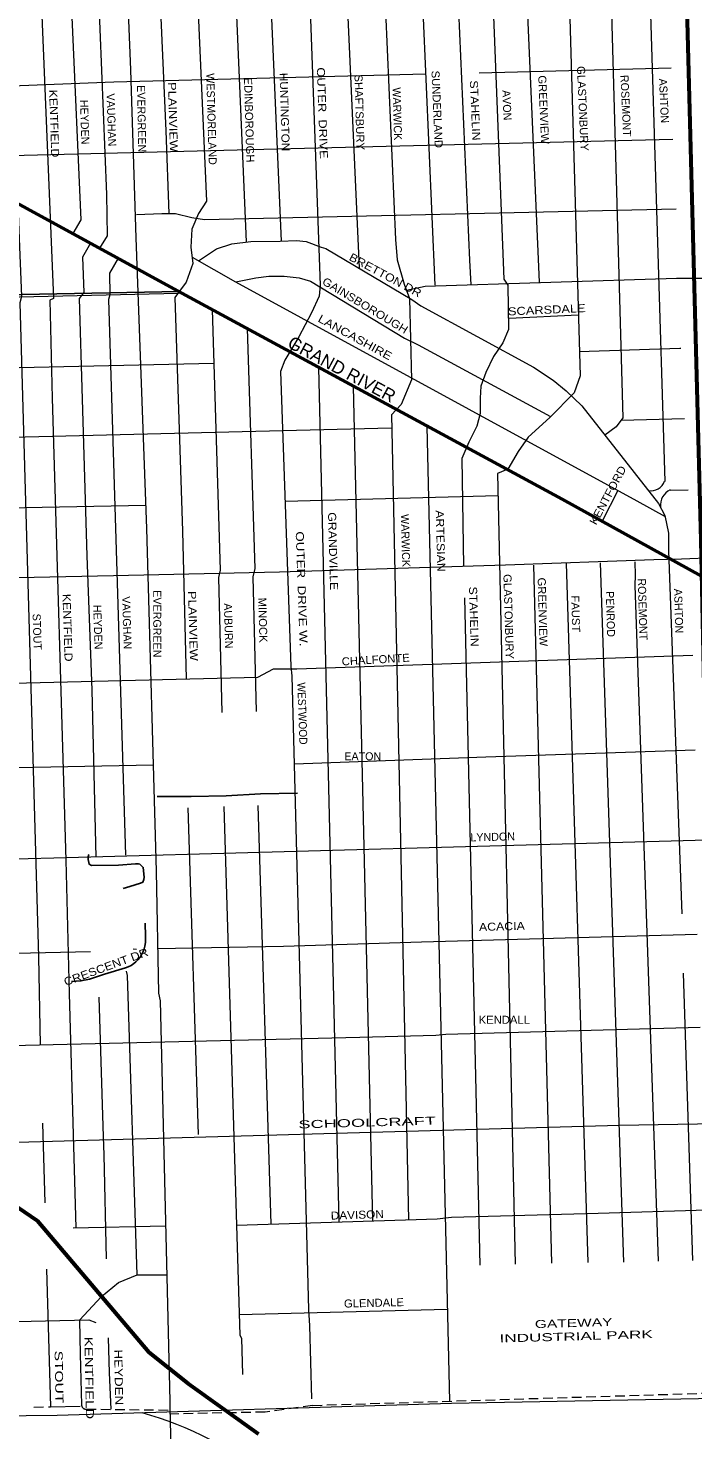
# Model space of a CAD drawing. Extents: x 34705 to 138605, y 34275 to 143551.
# Drawn here: x 47356 to 53584, y 117233 to 130370 of the extents above; entities that cross this region are included whole.
import ezdxf
from ezdxf.enums import TextEntityAlignment as Align

# ---------------------------------------------------------------- set-up
doc = ezdxf.new("R2010")
doc.units = 0
doc.header["$LTSCALE"] = 30
doc.linetypes.add('MEDIUM_DASHED', pattern=[4.5, 3, -1.5])
for name, color, linetype, lineweight in [('1', 7, 'Continuous', 13), ('11', 7, 'Continuous', 13), ('50', 7, 'Continuous', 13), ('51', 7, 'Continuous', 35)]:
    doc.layers.add(name, color=color, linetype=linetype, lineweight=lineweight)

msp = doc.modelspace()

# ---------------------------------------------------------------- linework, layer by layer
at = {"layer": '1'}
for p, q in [((49304.96, 130558.77), (49398.21, 128367.84)), ((51580.15, 129951.72), (53380.26, 129996.04)), ((49690.15, 129237.44), (53395.5, 129328)), ((46965.59, 129170.84), (49690.15, 129237.44)), ((51862.66, 127650.97), (52509.93, 127683.62)), ((50077.4, 127188.53), (50267.04, 119181.8)), ((50401.89, 127011.78), (50583, 119191.55)), ((52912.65, 126696.93), (53505.01, 126712.35)), ((51090.94, 126636.46), (51303.21, 117503.32)), ((49762.77, 125936.65), (51758.31, 125988.55)), ((52881.43, 126035.06), (52734.59, 125747.68)), ((53370.11, 126040.95), (53538.2, 126041.75)), ((52091.27, 125336.15), (52257.78, 118796.38)), ((52396.53, 125354.65), (52600.04, 118801.01)), ((52715.67, 125359.28), (52933.05, 118805.64)), ((51443.75, 125030.79), (51587.13, 118777.88)), ((48851.37, 123061.39), (48948.86, 120000.3)), ((49509.03, 123084.07), (49629.71, 119162.13)), ((53492.69, 121513.38), (53580.57, 118819.52)), ((47490.8, 120108.42), (47511.94, 119361.32)), ((47778.92, 119126.79), (48643.91, 119146.42)), ((47529.54, 118739.38), (47566.04, 117449.74)), ((47836.51, 118262.23), (48044.01, 118484.56)), ((48661.33, 118295.02), (48663.92, 118295.08)), ((49334.27, 118315.58), (51283.2, 118364.43)), ((47566.84, 117449.76), (47844.57, 117454.6))]:
    msp.add_line(p, q, dxfattribs=at)
at = {"layer": '1', "linetype": 'MEDIUM_DASHED'}
for p, q in [((48341.64, 121740.59), (48372.62, 121739.98)), ((50021.11, 117463.52), (53735.07, 117578.79)), ((47410.79, 117447.04), (47566.04, 117449.75)), ((47902.25, 117428.81), (48685.37, 117419.43))]:
    msp.add_line(p, q, dxfattribs=at)
at = {"layer": '1'}
for points in [[(47981.66, 141004.05), (48033.09, 139024.1), (48053.24, 138456.35), (48093.94, 137313.03), (48126.32, 135471.37), (48232.15, 132077.43), (48314.67, 129978.44), (48365.06, 128404.34), (48465.85, 125680.25), (48556.56, 122467.79), (48576.72, 121326.61), (48594.36, 121253.51), (48682.55, 117502.92), (48684.81, 117442.73), (48828.7, 111512.8), (48828.7, 111406.94), (48844.83, 109618.16), (48844.83, 109449.36), (48894.21, 107747.71), (49053.86, 101630.72)], [(51025.33, 141090.87), (51046.5, 140457.26), (50973.36, 140455.6), (51010.61, 138518.99), (51040.79, 138519.68), (51096.86, 136138.2), (51101.49, 135933.48), (51166.24, 135845.57), (51226.37, 133420.05), (51235.62, 133336.77), (51244.87, 133295.13), (51263.37, 133221.11), (51314.25, 130944.79), (51346.62, 130863.83), (51379, 130748.16), (51490, 128194.25), (51502.9, 127965.17)], [(50249.89, 135848.29), (50319.84, 133240.76), (50338.34, 133180.62), (50393.84, 130623.24), (50347.59, 130539.96), (50456.7, 128119.39)], [(50573.64, 135857.98), (50643.6, 133250.02), (50657.47, 133208.38), (50722.23, 130646.38), (50703.73, 130526.08), (50796.23, 128387.42), (50814.73, 128197.73), (50879.48, 127971.02), (50930.36, 127836.85), (50948.86, 127073.45), (50851.73, 126842.12), (50759.23, 126744.96), (50920.25, 119201.95)], [(50874.64, 135866.99), (50944.23, 133393.44), (50962.73, 133277.78), (50976.61, 133199.12), (51027.49, 130873.08), (51055.24, 130757.42), (51055.24, 130535.34), (51166.24, 127961.77)], [(52076.71, 135899.81), (52123.65, 133758.95), (52193.02, 130870.77), (52169.9, 130799.06), (52077.4, 130789.8), (52021.89, 130780.55), (52142.15, 127989.53)], [(47308.76, 135760.25), (47350.4, 134258.27), (47382.45, 133279.02), (47419.09, 132217.31), (47462.6, 131018.74), (47595.41, 127835.9), (47561.07, 127818.72), (47581.67, 126900.18), (47709.91, 122571.45), (47741.39, 121322.48), (47780.32, 119892.55), (47802.67, 119126.89)], [(47601.7, 135769.02), (47610.36, 135470.69), (47650.37, 134155.19), (47677.85, 133301.93), (47748.84, 131000.41), (47764.87, 130472.42), (47849.59, 128573.49), (47775.79, 128444.97)], [(47852.57, 135776.53), (47870.93, 135457.68), (47906.84, 134178.1), (47936.61, 133279.02), (47973.25, 132219.6), (48012.18, 130750.73), (48090.03, 128810.56), (48096.9, 128422.3), (48026.31, 128308.23)], [(47021.15, 134479.41), (47155.75, 130537.71), (47192.39, 130418.59), (47293.15, 127855.37), (47279.41, 127795.82), (47452.87, 121666.08), (47468.78, 120842.41)], [(49945.58, 134492.76), (50040.7, 130850.55), (50005.42, 130782.5), (49997.86, 130540.52), (50093.61, 127959.47), (50083.53, 127858.64), (50010.46, 127699.85), (49892.03, 127475.52), (49761.01, 127256.23), (49720.69, 127152.26), (49816.44, 124386.57), (49826.52, 124298.35), (49982.74, 118358.02), (49992.82, 118211.82), (50011.81, 117525.07)], [(48490.61, 133169.11), (48521.92, 132064.83), (48566.64, 130621.18), (48599.4, 130464.91), (48647.27, 129406.27), (48674.42, 128632.53)], [(49655.33, 133193.56), (49718.17, 130911.05), (49640.06, 130790.06), (49627.46, 130679.15), (49727.69, 128374.34)], [(51601, 131284.86), (51605.63, 130956.36), (51633.38, 130877.71), (51679.63, 130831.44), (51707.38, 130720.4), (51813.76, 128017.29), (51850.76, 127961.77), (51855.39, 127545.37), (51804.51, 127420.45), (51716.63, 127290.9), (51642.63, 127142.85), (51596.38, 127013.3), (51591.75, 126902.26), (51591.75, 126758.84), (51559.38, 126638.54), (51485.38, 126490.49), (51420.62, 126337.81), (51434.26, 125327.84)], [(52553.79, 131261.72), (52553.79, 131021.14), (52526.04, 130956.36), (52489.03, 130896.22), (52456.66, 130812.94), (52456.66, 130664.88), (52433.53, 130609.36), (52428.91, 130567.72), (52526.04, 127110.46), (52470.53, 126953.16), (52243.9, 126721.82), (52040.39, 126536.76), (51947.89, 126402.59), (51850.76, 126236.03), (51753.63, 126196.7), (51920.14, 118787.13)], [(52882.17, 131270.98), (52891.42, 130998), (52859.05, 130910.1), (52812.79, 130845.32), (52928.42, 126717.2), (52863.67, 126633.92), (52759.2, 126555.53)], [(53192.06, 131284.86), (53201.31, 130896.22), (53192.06, 130849.95), (53178.18, 130808.31), (53320.03, 126122.33)], [(48948.84, 130538.06), (48949.65, 130511.53), (49027.76, 128748.4), (48952.16, 128632.46), (48889.17, 128486.27), (48881.61, 128317.39), (48899.25, 128163.63), (48836.26, 127989.71), (48783.34, 127916.62), (48730.43, 127843.52), (48803.5, 125655.04), (48835.71, 124271.35)], [(46047.64, 129793.56), (46960.31, 129819.95), (48157.87, 129867.44), (51080.94, 129939.42)], [(48371.53, 128622), (48608.93, 128632.55), (48735.55, 128632.55), (48888.54, 128595.61), (49009.88, 128574.5), (53425.77, 128674.66)], [(50901.75, 127912.29), (51076.59, 127951.78), (53429.51, 128025.66), (53735.5, 128025.66), (58802.7, 128162.87), (59905.3, 128215.65), (61846.72, 128284.25), (63556.01, 128358.13), (63587.66, 128358.13), (64447.59, 128389.8), (65614.81, 128410.91), (67682.84, 128463.68), (68864.58, 128479.51), (72639.26, 128541.52), (73551.93, 128552.07), (74601.78, 128562.63), (77161.76, 128625.95), (79066.25, 128678.73), (79790.99, 128701.73)], [(47939.8, 128355.45), (47865.62, 128221.87), (47879.36, 127892.02), (47835.85, 127834.76), (47863.33, 126891.01), (47906.84, 125424.43), (47953.33, 124166.79), (47991.26, 122600.09)], [(48951.23, 128189.26), (49120.67, 128300.08), (49263.11, 128347.58), (49442.48, 128368.69), (49716.81, 128373.97), (49869.8, 128379.24), (49959.49, 128368.69), (50101.93, 128315.92), (50144.13, 128305.36), (50951.3, 127825.13), (51035.71, 127767.08), (52090.83, 127191.85), (52275.48, 127070.47), (52396.81, 126970.2), (52543.21, 126830.36), (53261.72, 125916.12)], [(48892.49, 128222.59), (49300.04, 127991.37), (49912.01, 127658.9), (53057.74, 125938.65), (53323.67, 125792.57)], [(48200.28, 128213.28), (48118.13, 128072.89), (48123.17, 127868.73), (48110.57, 127825.88), (48269.31, 122620.29)], [(49301.46, 127990.6), (49489.96, 128028.31), (49611.3, 128044.14), (49753.74, 128044.14), (49896.18, 128028.31), (50001.69, 127996.64), (50882.72, 127463.63), (51009.33, 127400.31), (52250.44, 126728.5)], [(41439.59, 127717.9), (41636.79, 127718.72), (41865.41, 127714.3), (42250.53, 127714.3), (43127.6, 127724.86), (43217.28, 127756.52), (48761.16, 127885.97)], [(49080.47, 127731.54), (49156.26, 125291.45), (49138.63, 125220.88), (49171.38, 123954.93)], [(49407.75, 127553.27), (49478.79, 125304.06), (49461.15, 125228.44), (49491.39, 123965.01)], [(52519.62, 127338.98), (53461.16, 127371.28), (53471.43, 127371.51)], [(39016.09, 127054.55), (40477.93, 127075.75), (40562.34, 127081.02), (42883.6, 127086.3), (44889.65, 127144.35), (45000.43, 127144.35), (46145.24, 127165.46), (49096.07, 127229.34)], [(39035.59, 126401.44), (40724.71, 126427.53), (41115.04, 126427.53), (41916.92, 126427.53), (42580.01, 126431.39), (43166, 126439.1), (44149.07, 126462.24), (50761.79, 126624.85)], [(39073.76, 125736.85), (40516.53, 125764.23), (40612.91, 125764.23), (40829.76, 125768.08), (41180.58, 125764.23), (41862.94, 125764.23), (42583.86, 125764.23), (43285.51, 125779.65), (44496.99, 125814.36), (45807.75, 125852.92), (46189.42, 125856.78), (48457.74, 125899.57)], [(53261.71, 125916.12), (53321.56, 125803.44), (53353.94, 125636.88), (53353.94, 125470.32), (53478.82, 122068.58)], [(39941.51, 125093.75), (40528.09, 125108.63), (40663.03, 125097.06), (40744.94, 125108.63), (41581.52, 125112.49), (42287.01, 125112.49), (43300.93, 125116.35), (44878.65, 125170.34), (48156.52, 125239.75), (49710.15, 125274.46), (51827.61, 125340.02), (53217.9, 125389.91), (53477.78, 125395.11), (53786.04, 125409.43)], [(53039.43, 125368.53), (53044.05, 125243.61), (53039.43, 125146.45), (53256.81, 118814.89)], [(40914.75, 124129.1), (43212.26, 124136.81), (43354.9, 124132.95), (44281.1, 124159.95), (49507.13, 124287.78), (49653.37, 124366.55), (49872.73, 124366.55), (53583.68, 124493.23)], [(46916.68, 119921.92), (52891.98, 120088.09), (53990.71, 120107.37), (55409.41, 120130.51), (55891.31, 120149.79), (57164.48, 120188.36), (57866.12, 120199.93), (58563.91, 120223.06), (59011.11, 120234.63), (60333.44, 120284.77), (62664.85, 120381.18), (62942.42, 120535.44), (65811.63, 120620.28), (69640.78, 120751.4), (73304.16, 120847.81), (73350.43, 120847.81), (73385.12, 120959.64), (73489.21, 121113.9), (73728.23, 121252.73), (77495.7, 123154.91), (77576.66, 123220.47), (77676.9, 123382.44), (77895.97, 123692.55)], [(49852.8, 123476.41), (51645.45, 123541.96), (53604.5, 123605.39)], [(40933.12, 123337.57), (41905.35, 123337.57), (41978.6, 123333.72), (43223.82, 123341.43), (43362.61, 123337.57), (44543.25, 123376.14), (44998.16, 123391.56), (45869.44, 123418.56), (45965.82, 123414.7), (48528.39, 123465.41)], [(49189.02, 123073.99), (49340.21, 118121.08), (49355.33, 118093.36), (49363.22, 117751.65)], [(41099.62, 122454.45), (41458.15, 122462.16), (41766.57, 122469.88), (42005.59, 122473.73), (43281.65, 122493.01), (43412.73, 122485.3), (47717.02, 122597.14), (53834.22, 122766.82), (57551.33, 122855.98)], [(48569.31, 121745.04), (49749.94, 121768.07), (51041.43, 121806.63), (53623.93, 121880.52)], [(41430.27, 121772.11), (41639.34, 121602.18), (41701.03, 121575.18), (41824.39, 121571.33), (41959.32, 121582.9), (42028.72, 121590.61), (43250.81, 121617.6), (43408.87, 121613.75), (44011.24, 121629.17), (47939.67, 121717.87)], [(48274.35, 121533.3), (48284.43, 121492.97), (48375.94, 118687.65)], [(48284.31, 121493.44), (48284.43, 121492.97), (48375.94, 118687.65)], [(48020.24, 121288.1), (48059.69, 119980.74), (48064.27, 119811.23), (48088.34, 118835.59)], [(41106.93, 120675.49), (41284.67, 120679.54), (41450.44, 120683.39), (41674.04, 120687.25), (41781.99, 120691.1), (41959.32, 120714.24), (42051.85, 120718.1), (43281.65, 120741.24), (50463.84, 120914.78), (51177.05, 120934.06), (51269.57, 120941.77), (53653.08, 121008.37)], [(49308.73, 119152.22), (51188.61, 119210.23), (51323.54, 119225.66), (52696.95, 119264.22), (53718.57, 119295.08), (53733.85, 119295.33)], [(48044.01, 118484.56), (48203.94, 118615.99), (48376.45, 118687.67), (48654.04, 118687.68)], [(46026.05, 118221.66), (47924.77, 118264.2), (47989.98, 118241.07)], [(47836.51, 118262.23), (47844.87, 117942.07), (47857.16, 117469.03)], [(48106.54, 118097.8), (48114.65, 117769.13), (48129.68, 117427.52)]]:
    msp.add_lwpolyline(points, dxfattribs=at)
at = {"layer": '1', "lineweight": 53}
msp.add_lwpolyline([(35051.57, 135383.85), (35124.2, 135323.83), (40544.24, 132389.75), (44352.38, 130313.49), (48721.15, 127927.26), (52359.24, 125955.06), (53781.74, 125169.15), (55156.63, 124418.97), (56043.46, 123936.71), (56442.24, 123716.41), (57585, 123085.31), (70109.98, 116247.42), (80624.23, 110526.89), (82336.58, 109591.28)], dxfattribs=at)
at = {"layer": '1', "lineweight": 25}
for points in [[(37911.41, 127686.12), (38203.24, 127680.58), (38303.04, 127721.95), (38325.81, 127931.49), (38521.05, 128243.98), (39412.67, 127885.92), (39479.2, 127912.86), (39529.81, 127990.08), (39707.77, 127962.88), (39975.21, 127996.38), (40834.68, 127905.45), (41055.96, 127944.51), (41290.17, 127858.28), (41387.87, 127762.23), (48773.97, 127901.51)], [(48563.94, 123168.62), (48883.43, 123167.71), (49211.61, 123174.76), (49532.23, 123195), (49878.42, 123199.25)], [(47924.01, 122624.47), (47919.96, 122603.4), (47919.77, 122579.48), (47923.79, 122551.2), (47928.45, 122534.15), (47951.38, 122521.37), (48202.18, 122527.02)], [(48202.18, 122527.02), (48362.93, 122537.84), (48389.12, 122538.94), (48404.19, 122534.48), (48434.86, 122504.15), (48441.87, 122412.8), (48439.7, 122392.72), (48431.18, 122365.49), (48410.43, 122355.68), (48308.4, 122326.42), (48246.54, 122306.73)], [(48268.7, 121564.82), (48292.08, 121572.17), (48321.15, 121586.35), (48348.11, 121604.14), (48366.69, 121619.73), (48383.7, 121637.02), (48405.53, 121664.63), (48419.25, 121686.08), (48434.33, 121716.49), (48443.11, 121740.37), (48450.08, 121766.25), (48454.63, 121801.69), (48456.9, 121859.85), (48453.91, 121982.49)], [(47762.5, 121436.14), (47850.93, 121440.17), (47932.05, 121458.72), (48073.38, 121504.41), (48268.7, 121564.82)]]:
    msp.add_lwpolyline(points, dxfattribs=at)
at = {"layer": '1', "linetype": 'MEDIUM_DASHED'}
msp.add_lwpolyline([(50021.11, 117463.52), (49576.83, 117400.51), (48686.29, 117381.76)], dxfattribs=at)
at = {"layer": '1'}
for centre, radius, start, end in [((53190.67, 126172.47), 137.66, 260.60799, 338.69952), ((53437.08, 125899.04), 157.01, 115.05434, 186.39927)]:
    msp.add_arc(centre, radius, start, end, dxfattribs=at)
at = {"layer": '1', "linetype": 'MEDIUM_DASHED'}
msp.add_arc((47896.86, 117468.06), 39.62, 178.6386, 277.81809, dxfattribs=at)
at = {"layer": '50'}
msp.add_lwpolyline([(65035.62, 117740.68), (51320.84, 117480.65), (47627.27, 117368.44), (46180.25, 117354.42), (45362.54, 117350.68), (43373.91, 117338.95), (42070.05, 117290.03), (40546.95, 117248.5)], dxfattribs=at)
msp.add_arc((47551.28, 114253.58), 3258.47, 50.45194, 74.44351, dxfattribs=at)
at = {"layer": '51', "lineweight": 60}
for points in [[(53247.59, 141475.55), (53367.81, 136119.69), (53437.19, 134090.91), (53460.32, 134053.9), (53501.94, 131503.46), (53659.2, 125572.1), (53705.45, 123295.79), (53737.83, 121494.87), (53784.08, 121152.5), (53816.45, 120138.11), (53862.7, 118347.6), (53920.69, 117583.67), (53996.83, 116839.32), (53996.26, 116300.14), (54017.35, 115245.27), (54103.21, 113517.38), (54126.34, 110285.67), (54140.21, 108707.98), (54144.84, 108035.97), (54101.7, 107394.41), (54140.21, 105981.73), (54195.72, 103679.98), (54256.6, 101226.04)], [(37691, 119648.31), (39355.56, 119744.01), (39542.31, 119764.02), (39842.43, 119790.71), (42090.07, 119804.05), (42470.23, 119764.02), (43463.99, 119710.65), (46426.92, 119697.3), (46586.99, 119657.27), (46840.43, 119557.2), (47133.89, 119403.75), (47440.69, 119196.93), (48487.8, 117962.66), (48854.63, 117669.11), (49514.91, 117195.42)]]:
    msp.add_lwpolyline(points, dxfattribs=at)

# ---------------------------------------------------------------- texts
at = {"layer": '11'}
for s, height, rotation, p in [('WESTMORELAND', 75, 271.61, (49036.8, 129516.26)), ('EVERGREEN', 75, 271.007, (48382.11, 129520.14)), ('WARWICK', 75, 271.611, (50777.46, 129565.39)), ('ROSEMONT', 75, 272.539, (52917.45, 129639.61)), ('ASHTON', 75, 272.537, (53275.01, 129686.58)), ('HEYDEN', 75, 271.867, (47849.08, 129487.26)), ('VAUGHAN', 75, 271.867, (48099.34, 129508.17)), ('AVON', 75, 272.539, (51804.28, 129645.42)), ('GRAND RIVER', 120, 331.683, (50267.09, 127119.89)), ('WARWICK', 75, 271.579, (50854.24, 125566.56)), ('ROSEMONT', 75, 271.653, (53075.5, 124922.37)), ('EVERGREEN', 75, 270, (48528.58, 124786.66)), ('PENROD', 75, 271.656, (52774.07, 124877.21)), ('ASHTON', 75, 271.654, (53413.13, 124906.69)), ('HEYDEN', 75, 271.867, (47972.66, 124755.14)), ('VAUGHAN', 75, 271.867, (48244.49, 124796.11)), ('AUBURN', 75, 271.579, (49196.31, 124767.44)), ('STOUT', 75, 271.868, (47403.68, 124711.1)), ('LYNDON', 75, 1.58, (51709.02, 122753.25))]:
    msp.add_text(s, height=height, rotation=rotation, dxfattribs=at).set_placement(p, align=Align.CENTER)
for s, rotation, width, p in [('HUNTINGTON', 271.611, 1.1, (49722.38, 129581.81)), ('OUTER  DRIVE', 271.983, 1.2, (50075.5, 129572.65)), ('SHAFTSBURY', 271.609, 1.05, (50423.24, 129580.16)), ('SUNDERLAND', 272.538, 1.05, (51150.27, 129606.71)), ('GLASTONBURY', 272.539, 1.05, (52514.87, 129614.33)), ('PLAINVIEW', 271.611, 1.2, (48675.89, 129534.67)), ('EDINBOROUGH', 271.611, 1.05, (49389.93, 129507.44)), ('STAHELIN', 272.54, 1.15, (51506.3, 129596.11)), ('GREENVIEW', 272.537, 1.05, (52148.2, 129603.66)), ('KENTFIELD', 271.867, 1.15, (47563.5, 129474.42)), ('BRETTON DR', 331.684, 1.15, (50685.3, 128021.94)), ('GAINSBOROUGH', 328.827, 1.1, (50494.28, 127738)), ('SCARSDALE ', 2.519, 1.2, (52233.08, 127693.33)), ('LANCASHIRE', 331.362, 1.2, (50401.05, 127438.8)), ('KENTFORD', 61.765, 1.1, (52820.27, 125974.44)), ('GRANDVILLE', 271.58, 1.15, (50175.47, 125466.53)), ('ARTESIAN', 271.576, 1.15, (51182.29, 125562.57)), ('OUTER  DRIVE W.', 271.983, 1.25, (49881.71, 125112.82)), ('GLASTONBURY', 271.655, 1.05, (51820.11, 124854.3)), ('GREENVIEW', 271.654, 1.05, (52138.56, 124897.82)), ('PLAINVIEW', 271.582, 1.2, (48863.42, 124766.28)), ('STAHELIN', 271.655, 1.15, (51494.34, 124853.54)), ('KENTFIELD', 271.866, 1.15, (47688.58, 124749.78)), ('MINOCK', 271.582, 1.05, (49517.85, 124820.98)), ('FAUST', 271.655, 1.05, (52448.33, 124879.77)), ('CHALFONTE', 3.368, 1.05, (50614.62, 124414.84)), ('WESTWOOD', 271.983, 0.95, (49888.05, 123945.56)), ('ACACIA', 1.581, 1.15, (51795.2, 121914.26)), ('CRESCENT DR', 20.227, 1.15, (48098.26, 121536.76)), ('SCHOOLCRAFT', 1.635, 1.7, (50533.13, 120076.39)), ('DAVISON', 1.79, 1.1, (50440.86, 119211.47)), ('GLENDALE', 1.436, 1.05, (50596.56, 118386.63)), ('GATEWAY ', 1.665, 1.45, (52487.44, 118198.15)), ('INDUSTRIAL PARK', 1.665, 1.6, (52491.08, 118073.2)), ('KENTFIELD   ', 271.069, 1.4, (47892.47, 117661.25)), ('HEYDEN  ', 271.069, 1.25, (48168.29, 117690.63)), ('STOUT     ', 271.07, 1.45, (47610.68, 117627.93))]:
    msp.add_text(s, height=75, rotation=rotation, dxfattribs=dict(at, width=width)).set_placement(p, align=Align.CENTER)
msp.add_text('EATON', height=75, dxfattribs=at).set_placement((50490.98, 123508.38), align=Align.CENTER)
at = {"layer": '11', "width": 1.05}
msp.add_text('KENDALL', height=75, dxfattribs=at).set_placement((51816.79, 121039.21), align=Align.CENTER)

doc.saveas('drawing.dxf')
